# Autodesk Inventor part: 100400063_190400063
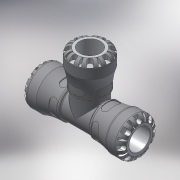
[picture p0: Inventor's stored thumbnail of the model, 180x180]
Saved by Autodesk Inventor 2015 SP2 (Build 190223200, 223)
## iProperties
Created: 2016-12
Part Number: 100400063_190400063
Material: Generic
Description: PLASSON TEE 63X63X63 SERIES 1
Document SubType Name: Modeling
Designer: KIM
Mass: 664.223 g
Surface Area: 733.008 cm^2
Volume: 474.445 cm^3
Density: 1 g/cm^3
Appearance: Default
Author: KIM
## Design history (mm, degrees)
derived "1004.ipt"
feature "Solid1::1004.ipt"
tag "TaggingFeature1"
body "Solid1"
other parameters: "d9" = 12.125, "d11" = 103, "d12" = 78.75, "d230" = 103, "d231" = 78.75, "d232" = 12.125, "d1" = 37.8, "d2" = 63, "d3" = 78.75, "d4" = 103, "d8" = 87.55, "d13" = 9.7, "d14" = 9.7, "d15" = 0, "d17" = 360 deg, "d19" = 8 deg, "d20" = 1.26, "d21" = 1.26, "d22" = 8 deg, "d24" = 0, "d26" = 360 deg, "d33" = 10.3, "d43" = 80.34, "d51" = 1.03, "d54" = 22.05, "d55" = 13.86, "d57" = 19.012, "d58" = 0, "d74" = 0, "d77" = 5.25, "d79" = 80.34, "d80" = 262, "d82" = 1.26, "d115" = 360 deg, "d139" = 9.7, "d140" = 0, "d142" = 360 deg, "d207" = 90 deg, "d209" = 37.8, "d210" = 63, "d211" = 78.75, "d212" = 103, "d213" = 87.55, "d215" = 80.34, "d216" = 5.25, "d225" = 147, "d228" = 18.7425, "d229" = 9.7, "d233" = 9.7, "d234" = 0, "d236" = 360 deg, "d238" = 8 deg, "d239" = 8 deg, "d240" = 1.26, "d241" = 1.26, "d243" = 0, "d245" = 360 deg, "d247" = 2.06, "d248" = 5.4, "d249" = 5.4, "d250" = 18.7425, "d252" = 22.05, "d253" = 14.49, "d254" = 19.012, "d255" = 0, "d257" = 360 deg, "d259" = 1.26, "d261" = 0, "d262" = 2.06, "d264" = 0, "d266" = 0, "d267" = 1.03, "d_" = 63, "E_" = 103, "A_" = 147, "H_" = 262
